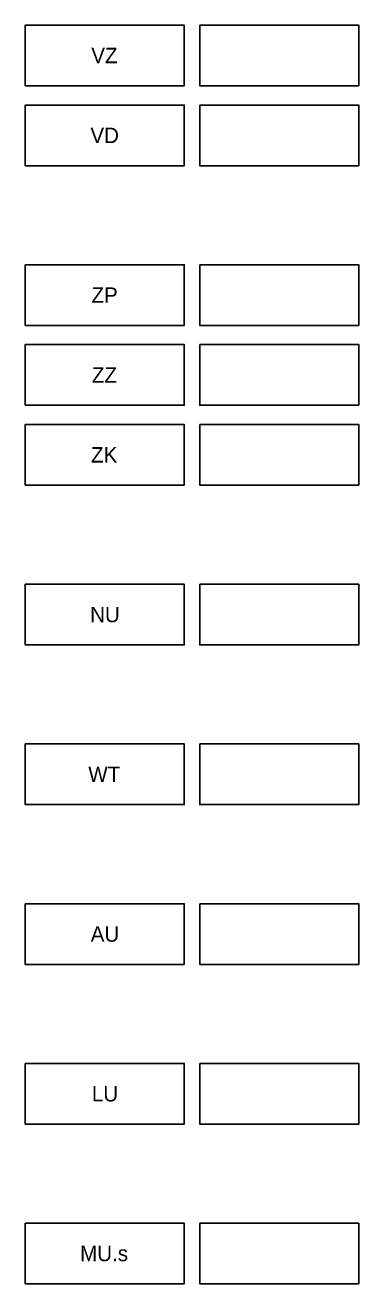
# Model space of a CAD drawing. Extents: x -439236 to -436121, y -1128919 to -1121098.
# Drawn here: x -438186 to -437968, y -1128328 to -1127508 of the extents above; entities that cross this region are included whole.
import ezdxf

# ---------------------------------------------------------------- set-up
doc = ezdxf.new("R2010")
doc.units = 0
for name, color, linetype in [('AU - zemedelske vseobecne', 7, 'Continuous'), ('LU - lesni vseobecne', 7, 'Continuous'), ('MU - smisene nezastaveneho uzemi vseobecne', 7, 'Continuous'), ('NU - prirodni vseobecne', 7, 'Continuous'), ('STAV', 7, 'Continuous'), ('VD - vyroba drobna a sluzby', 7, 'Continuous'), ('Vrstva 1', 7, 'Continuous'), ('VZ - vyroba zemedelska a lesnicka', 7, 'Continuous'), ('WT - vodni a vodnich toku', 7, 'Continuous'), ('ZK - zelen krajinna', 7, 'Continuous'), ('ZP - zelen - parky a parkove upravene plochy', 7, 'Continuous'), ('ZZ - zelen - zahrady a sady', 7, 'Continuous')]:
    doc.layers.add(name, color=color, linetype=linetype)

msp = doc.modelspace()

# ---------------------------------------------------------------- linework, layer by layer
at = {"layer": 'AU - zemedelske vseobecne'}
msp.add_lwpolyline([(-438185.55, -1128080.47), (-438081.93, -1128080.47), (-438081.93, -1128119.97), (-438185.55, -1128119.97)], close=True, dxfattribs=at)
at = {"layer": 'LU - lesni vseobecne'}
msp.add_lwpolyline([(-438185.55, -1128184.5), (-438081.93, -1128184.5), (-438081.93, -1128224.01), (-438185.55, -1128224.01)], close=True, dxfattribs=at)
at = {"layer": 'MU - smisene nezastaveneho uzemi vseobecne'}
msp.add_lwpolyline([(-438185.55, -1128288.54), (-438081.93, -1128288.54), (-438081.93, -1128328.04), (-438185.55, -1128328.04)], close=True, dxfattribs=at)
at = {"layer": 'NU - prirodni vseobecne'}
msp.add_lwpolyline([(-438185.55, -1127872.39), (-438081.93, -1127872.39), (-438081.93, -1127911.9), (-438185.55, -1127911.9)], close=True, dxfattribs=at)
at = {"layer": 'VD - vyroba drobna a sluzby'}
msp.add_lwpolyline([(-438185.55, -1127560.28), (-438081.93, -1127560.28), (-438081.93, -1127599.79), (-438185.55, -1127599.79)], close=True, dxfattribs=at)
at = {"layer": 'Vrstva 1'}
for points in [[(-438185.55, -1127508.27), (-438081.93, -1127508.27), (-438081.93, -1127547.77), (-438185.55, -1127547.77)], [(-438071.93, -1127508.27), (-437968.32, -1127508.27), (-437968.32, -1127547.77), (-438071.93, -1127547.77)], [(-438185.55, -1127560.28), (-438081.93, -1127560.28), (-438081.93, -1127599.79), (-438185.55, -1127599.79)], [(-438071.93, -1127560.28), (-437968.32, -1127560.28), (-437968.32, -1127599.79), (-438071.93, -1127599.79)], [(-438185.55, -1127664.32), (-438081.93, -1127664.32), (-438081.93, -1127703.82), (-438185.55, -1127703.82)], [(-438071.93, -1127664.32), (-437968.32, -1127664.32), (-437968.32, -1127703.82), (-438071.93, -1127703.82)], [(-438185.55, -1127716.34), (-438081.93, -1127716.34), (-438081.93, -1127755.84), (-438185.55, -1127755.84)], [(-438071.93, -1127716.34), (-437968.32, -1127716.34), (-437968.32, -1127755.84), (-438071.93, -1127755.84)], [(-438185.55, -1127768.36), (-438081.93, -1127768.36), (-438081.93, -1127807.86), (-438185.55, -1127807.86)], [(-438071.93, -1127768.36), (-437968.32, -1127768.36), (-437968.32, -1127807.86), (-438071.93, -1127807.86)], [(-438185.55, -1127872.39), (-438081.93, -1127872.39), (-438081.93, -1127911.9), (-438185.55, -1127911.9)], [(-438071.93, -1127872.39), (-437968.32, -1127872.39), (-437968.32, -1127911.9), (-438071.93, -1127911.9)], [(-438185.55, -1127976.43), (-438081.93, -1127976.43), (-438081.93, -1127976.43), (-438081.93, -1128015.93), (-438185.55, -1128015.93)], [(-438071.93, -1127976.43), (-437968.32, -1127976.43), (-437968.32, -1128015.93), (-438071.93, -1128015.93)], [(-438185.55, -1128080.47), (-438081.93, -1128080.47), (-438081.93, -1128119.97), (-438185.55, -1128119.97)], [(-438071.93, -1128080.47), (-437968.32, -1128080.47), (-437968.32, -1128119.97), (-438071.93, -1128119.97)], [(-438185.55, -1128184.5), (-438081.93, -1128184.5), (-438081.93, -1128184.5), (-438081.93, -1128224.01), (-438185.55, -1128224.01)], [(-438071.93, -1128184.5), (-437968.32, -1128184.5), (-437968.32, -1128224.01), (-438071.93, -1128224.01)], [(-438185.55, -1128288.54), (-438081.93, -1128288.54), (-438081.93, -1128288.54), (-438081.93, -1128328.04), (-438185.55, -1128328.04)], [(-438071.93, -1128288.54), (-437968.32, -1128288.54), (-437968.32, -1128328.04), (-438071.93, -1128328.04)]]:
    msp.add_lwpolyline(points, close=True, dxfattribs=at)
at = {"layer": 'VZ - vyroba zemedelska a lesnicka'}
msp.add_lwpolyline([(-438185.55, -1127508.27), (-438081.93, -1127508.27), (-438081.93, -1127547.77), (-438185.55, -1127547.77)], close=True, dxfattribs=at)
at = {"layer": 'WT - vodni a vodnich toku'}
msp.add_lwpolyline([(-438185.55, -1127976.43), (-438081.93, -1127976.43), (-438081.93, -1128015.93), (-438185.55, -1128015.93)], close=True, dxfattribs=at)
at = {"layer": 'ZK - zelen krajinna'}
msp.add_lwpolyline([(-438185.55, -1127768.36), (-438081.93, -1127768.36), (-438081.93, -1127807.86), (-438185.55, -1127807.86)], close=True, dxfattribs=at)
at = {"layer": 'ZP - zelen - parky a parkove upravene plochy'}
msp.add_lwpolyline([(-438185.55, -1127664.32), (-438081.93, -1127664.32), (-438081.93, -1127703.82), (-438185.55, -1127703.82)], close=True, dxfattribs=at)
at = {"layer": 'ZZ - zelen - zahrady a sady'}
msp.add_lwpolyline([(-438185.55, -1127716.34), (-438081.93, -1127716.34), (-438081.93, -1127755.84), (-438185.55, -1127755.84)], close=True, dxfattribs=at)

# ---------------------------------------------------------------- texts
at = {"layer": 'STAV'}
for s, p in [('VZ', (-438142.5, -1127533.02)), ('VD', (-438143.08, -1127585.04)), ('ZP', (-438142.37, -1127689.07)), ('ZZ', (-438142.1, -1127741.09)), ('ZK', (-438142.66, -1127793.11)), ('NU', (-438143.27, -1127897.15)), ('WT', (-438144.46, -1128001.18)), ('AU', (-438142.88, -1128105.22)), ('LU', (-438142.11, -1128209.26)), ('MU.s', (-438149.77, -1128313.29))]:
    msp.add_text(s, height=10, dxfattribs=at).set_placement(p)

doc.saveas('drawing.dxf')
